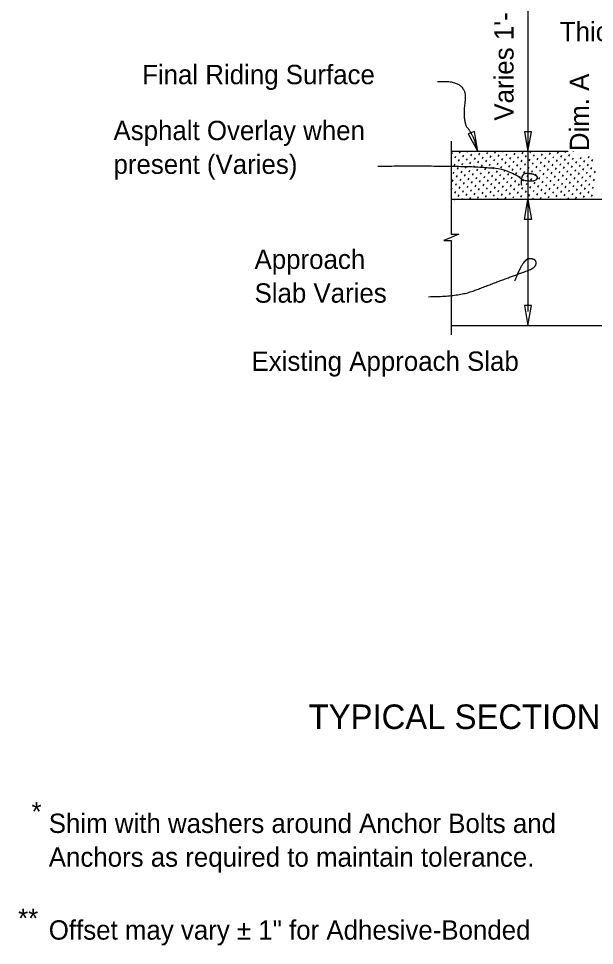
# Model space of a CAD drawing. Extents: x 21629.5 to 21698.8, y 56199.4 to 56237.6.
# Drawn here: x 21650.35 to 21656.36, y 56218.59 to 56228.26 of the extents above; entities that cross this region are included whole.
import ezdxf

# ---------------------------------------------------------------- set-up
doc = ezdxf.new("R2010")
doc.units = 0
for name, color, linetype in [('Dimension', 7, 'Continuous'), ('ExistSuperStruct', 7, 'Continuous'), ('Miscellaneous', 7, 'Continuous'), ('TextStructures', 7, 'Continuous')]:
    doc.layers.add(name, color=color, linetype=linetype)

msp = doc.modelspace()

# ---------------------------------------------------------------- linework, layer by layer
at = {"layer": 'Dimension'}
msp.add_line((21655.6632, 56232.202), (21655.6632, 56225.2019), dxfattribs=at)
for points in [[(21655.1407, 56226.8686), (21655.1069, 56227.0771), (21655.0401, 56227.0543)], [(21655.6634, 56226.8686), (21655.6987, 56227.0769), (21655.6281, 56227.0769)], [(21655.6633, 56226.3686), (21655.6985, 56226.1603), (21655.628, 56226.1603)], [(21655.6633, 56225.0569), (21655.6985, 56225.2652), (21655.628, 56225.2652)]]:
    msp.add_lwpolyline(points, close=True, dxfattribs=at)
msp.add_lwpolyline([(21654.8631, 56226.9778), (21654.8631, 56226.0088), (21654.9406, 56226.0088), (21654.8631, 56225.9751), (21654.7856, 56225.9413), (21654.8631, 56225.9413), (21654.8631, 56224.9569)], dxfattribs=at)
for points in [[(21654.7213, 56227.5984), (21655.0349, 56227.6253), (21654.9791, 56227.1758), (21655.0896, 56227.0538), (21655.1407, 56226.8686)], [(21654.0966, 56226.7169), (21654.4564, 56226.7236), (21655.4463, 56226.7072), (21655.5881, 56226.5767), (21655.693, 56226.5583), (21655.7624, 56226.5767), (21655.7624, 56226.6178), (21655.6916, 56226.6405), (21655.6051, 56226.6405), (21655.588, 56226.5402), (21655.595, 56226.5181)], [(21654.6274, 56225.3564), (21654.9374, 56225.3564), (21655.2737, 56225.485), (21655.5639, 56225.5938), (21655.7486, 56225.6598), (21655.7486, 56225.7521), (21655.6101, 56225.7521), (21655.5244, 56225.518)]]:
    msp.add_open_spline(points, degree=2, dxfattribs=at)
at = {"layer": 'ExistSuperStruct'}
for p, q in [((21658.7963, 56226.3686), (21654.863, 56226.3686)), ((21654.863, 56225.0569), (21660.2645, 56225.0569))]:
    msp.add_line(p, q, dxfattribs=at)
at = {"layer": 'Miscellaneous'}
for p, q in [((21656.0825, 56226.8686), (21654.863, 56226.8686)), ((21654.863, 56226.7712), (21654.8658, 56226.776)), ((21654.8658, 56226.8421), (21654.8755, 56226.8589)), ((21654.9024, 56226.8055), (21654.9121, 56226.8223)), ((21654.939, 56226.7689), (21654.9487, 56226.7857)), ((21654.9487, 56226.8518), (21654.9584, 56226.8686)), ((21654.9853, 56226.8152), (21654.995, 56226.832)), ((21655.0219, 56226.7786), (21655.0316, 56226.7954)), ((21655.0316, 56226.8616), (21655.0357, 56226.8686)), ((21655.0682, 56226.825), (21655.078, 56226.8418)), ((21655.1048, 56226.7884), (21655.1146, 56226.8052)), ((21655.1512, 56226.8347), (21655.1609, 56226.8515)), ((21655.1878, 56226.7981), (21655.1975, 56226.8149)), ((21655.2244, 56226.7615), (21655.2341, 56226.7783)), ((21655.2341, 56226.8444), (21655.2438, 56226.8612)), ((21655.2707, 56226.8078), (21655.2804, 56226.8246)), ((21655.3073, 56226.7712), (21655.317, 56226.788)), ((21655.317, 56226.8541), (21655.3254, 56226.8686)), ((21655.3537, 56226.8175), (21655.3634, 56226.8343)), ((21655.3903, 56226.7809), (21655.4, 56226.7977)), ((21655.4, 56226.8639), (21655.4027, 56226.8686)), ((21655.4366, 56226.8272), (21655.4463, 56226.844)), ((21655.4732, 56226.7906), (21655.4829, 56226.8074)), ((21655.5195, 56226.837), (21655.5293, 56226.8538)), ((21655.5561, 56226.8004), (21655.5659, 56226.8172)), ((21655.5927, 56226.7638), (21655.6025, 56226.7805)), ((21655.6025, 56226.8467), (21655.6122, 56226.8635)), ((21655.6391, 56226.8101), (21655.6488, 56226.8269)), ((21655.6757, 56226.7735), (21655.6854, 56226.7903)), ((21655.6854, 56226.8564), (21655.6925, 56226.8686)), ((21655.722, 56226.8198), (21655.7317, 56226.8366)), ((21655.7586, 56226.7832), (21655.7683, 56226.8)), ((21655.7683, 56226.8661), (21655.7698, 56226.8686)), ((21655.805, 56226.8295), (21655.8147, 56226.8463)), ((21655.8416, 56226.7929), (21655.8513, 56226.8097)), ((21655.8879, 56226.8393), (21655.8976, 56226.856)), ((21655.9245, 56226.8026), (21655.9342, 56226.8194)), ((21655.9611, 56226.766), (21655.9708, 56226.7828)), ((21655.9708, 56226.849), (21655.9805, 56226.8658)), ((21656.0074, 56226.8124), (21656.0172, 56226.8292)), ((21656.044, 56226.7758), (21656.0538, 56226.7926)), ((21656.0538, 56226.8587), (21656.0595, 56226.8686)), ((21656.0904, 56226.8221), (21656.1001, 56226.8389)), ((21656.127, 56226.7855), (21656.1367, 56226.8023)), ((21656.1367, 56226.8684), (21656.1368, 56226.8686)), ((21656.2099, 56226.7952), (21656.2196, 56226.812)), ((21656.2929, 56226.8049), (21656.3026, 56226.8217)), ((21656.3295, 56226.7683), (21656.3392, 56226.7851)), ((21654.8926, 56226.7226), (21654.9024, 56226.7394)), ((21654.9292, 56226.686), (21654.939, 56226.7028)), ((21654.9756, 56226.7323), (21654.9853, 56226.7491)), ((21655.0122, 56226.6957), (21655.0219, 56226.7125)), ((21655.0585, 56226.742), (21655.0682, 56226.7588)), ((21655.0951, 56226.7054), (21655.1048, 56226.7222)), ((21655.1317, 56226.6688), (21655.1414, 56226.6856)), ((21655.1414, 56226.7517), (21655.1512, 56226.7685)), ((21655.1781, 56226.7151), (21655.1878, 56226.7319)), ((21655.2147, 56226.6785), (21655.2244, 56226.6953)), ((21655.261, 56226.7249), (21655.2707, 56226.7417)), ((21655.2976, 56226.6883), (21655.3073, 56226.7051)), ((21655.3439, 56226.7346), (21655.3537, 56226.7514)), ((21655.3805, 56226.698), (21655.3903, 56226.7148)), ((21655.4269, 56226.7443), (21655.4366, 56226.7611)), ((21655.4635, 56226.7077), (21655.4732, 56226.7245)), ((21655.5001, 56226.6711), (21655.5098, 56226.6879)), ((21655.5098, 56226.754), (21655.5195, 56226.7708)), ((21655.5464, 56226.7174), (21655.5561, 56226.7342)), ((21655.583, 56226.6808), (21655.5927, 56226.6976)), ((21655.6294, 56226.7271), (21655.6391, 56226.7439)), ((21655.666, 56226.6905), (21655.6757, 56226.7073)), ((21655.7123, 56226.7369), (21655.722, 56226.7537)), ((21655.7489, 56226.7003), (21655.7586, 56226.7171)), ((21655.7855, 56226.6637), (21655.7952, 56226.6804)), ((21655.7952, 56226.7466), (21655.805, 56226.7634)), ((21655.8318, 56226.71), (21655.8416, 56226.7268)), ((21655.8684, 56226.6734), (21655.8782, 56226.6902)), ((21655.8782, 56226.7563), (21655.8879, 56226.7731)), ((21655.9148, 56226.7197), (21655.9245, 56226.7365)), ((21655.9514, 56226.6831), (21655.9611, 56226.6999)), ((21655.9977, 56226.7294), (21656.0074, 56226.7462)), ((21656.0343, 56226.6928), (21656.044, 56226.7096)), ((21656.0806, 56226.7392), (21656.0904, 56226.7559)), ((21656.1173, 56226.7025), (21656.127, 56226.7193)), ((21656.1539, 56226.6659), (21656.1636, 56226.6827)), ((21656.1636, 56226.7489), (21656.1733, 56226.7657)), ((21656.2002, 56226.7123), (21656.2099, 56226.7291)), ((21656.2368, 56226.6757), (21656.2465, 56226.6925)), ((21656.2465, 56226.7586), (21656.2562, 56226.7754)), ((21656.2831, 56226.722), (21656.2929, 56226.7388)), ((21656.3197, 56226.6854), (21656.3295, 56226.7022)), ((21654.8829, 56226.6396), (21654.8926, 56226.6564)), ((21654.9195, 56226.603), (21654.9292, 56226.6198)), ((21654.9561, 56226.5664), (21654.9659, 56226.5832)), ((21654.9659, 56226.6494), (21654.9756, 56226.6662)), ((21655.0025, 56226.6128), (21655.0122, 56226.6296)), ((21655.0391, 56226.5762), (21655.0488, 56226.5929)), ((21655.0488, 56226.6591), (21655.0585, 56226.6759)), ((21655.0854, 56226.6225), (21655.0951, 56226.6393)), ((21655.122, 56226.5859), (21655.1317, 56226.6027)), ((21655.1683, 56226.6322), (21655.1781, 56226.649)), ((21655.2049, 56226.5956), (21655.2147, 56226.6124)), ((21655.2513, 56226.6419), (21655.261, 56226.6587)), ((21655.2879, 56226.6053), (21655.2976, 56226.6221)), ((21655.3245, 56226.5687), (21655.3342, 56226.5855)), ((21655.3342, 56226.6516), (21655.3439, 56226.6684)), ((21655.3708, 56226.615), (21655.3805, 56226.6318)), ((21655.4074, 56226.5784), (21655.4171, 56226.5952)), ((21655.4171, 56226.6614), (21655.4269, 56226.6782)), ((21655.4538, 56226.6248), (21655.4635, 56226.6416)), ((21655.4904, 56226.5882), (21655.5001, 56226.605)), ((21655.5367, 56226.6345), (21655.5464, 56226.6513)), ((21655.5733, 56226.5979), (21655.583, 56226.6147)), ((21655.6196, 56226.6442), (21655.6294, 56226.661)), ((21655.6562, 56226.6076), (21655.666, 56226.6244)), ((21655.6928, 56226.571), (21655.7026, 56226.5878)), ((21655.7026, 56226.6539), (21655.7123, 56226.6707)), ((21655.7392, 56226.6173), (21655.7489, 56226.6341)), ((21655.7758, 56226.5807), (21655.7855, 56226.5975)), ((21655.8221, 56226.627), (21655.8318, 56226.6438)), ((21655.8587, 56226.5904), (21655.8684, 56226.6072)), ((21655.9051, 56226.6368), (21655.9148, 56226.6536)), ((21655.9417, 56226.6002), (21655.9514, 56226.617)), ((21655.988, 56226.6465), (21655.9977, 56226.6633)), ((21656.0246, 56226.6099), (21656.0343, 56226.6267)), ((21656.0612, 56226.5733), (21656.0709, 56226.5901)), ((21656.0709, 56226.6562), (21656.0806, 56226.673)), ((21656.1075, 56226.6196), (21656.1173, 56226.6364)), ((21656.1441, 56226.583), (21656.1539, 56226.5998)), ((21656.1905, 56226.6293), (21656.2002, 56226.6461)), ((21656.2271, 56226.5927), (21656.2368, 56226.6095)), ((21656.2734, 56226.6391), (21656.2831, 56226.6558)), ((21656.31, 56226.6024), (21656.3197, 56226.6192)), ((21656.3466, 56226.5658), (21656.3563, 56226.5826)), ((21656.3563, 56226.6488), (21656.3661, 56226.6656)), ((21654.8635, 56226.4738), (21654.8732, 56226.4906)), ((21654.8732, 56226.5567), (21654.8829, 56226.5735)), ((21654.9098, 56226.5201), (21654.9195, 56226.5369)), ((21654.9464, 56226.4835), (21654.9561, 56226.5003)), ((21654.9927, 56226.5298), (21655.0025, 56226.5466)), ((21655.0293, 56226.4932), (21655.0391, 56226.51)), ((21655.0757, 56226.5395), (21655.0854, 56226.5563)), ((21655.1123, 56226.5029), (21655.122, 56226.5197)), ((21655.1586, 56226.5493), (21655.1683, 56226.5661)), ((21655.1952, 56226.5127), (21655.2049, 56226.5295)), ((21655.2318, 56226.4761), (21655.2415, 56226.4928)), ((21655.2415, 56226.559), (21655.2513, 56226.5758)), ((21655.2782, 56226.5224), (21655.2879, 56226.5392)), ((21655.3148, 56226.4858), (21655.3245, 56226.5026)), ((21655.3611, 56226.5321), (21655.3708, 56226.5489)), ((21655.3977, 56226.4955), (21655.4074, 56226.5123)), ((21655.444, 56226.5418), (21655.4538, 56226.5586)), ((21655.4806, 56226.5052), (21655.4904, 56226.522)), ((21655.527, 56226.5515), (21655.5367, 56226.5683)), ((21655.5636, 56226.5149), (21655.5733, 56226.5317)), ((21655.6002, 56226.4783), (21655.6099, 56226.4951)), ((21655.6099, 56226.5613), (21655.6196, 56226.5781)), ((21655.6465, 56226.5247), (21655.6562, 56226.5415)), ((21655.6831, 56226.4881), (21655.6928, 56226.5049)), ((21655.7295, 56226.5344), (21655.7392, 56226.5512)), ((21655.7661, 56226.4978), (21655.7758, 56226.5146)), ((21655.8124, 56226.5441), (21655.8221, 56226.5609)), ((21655.849, 56226.5075), (21655.8587, 56226.5243)), ((21655.8856, 56226.4709), (21655.8953, 56226.4877)), ((21655.8953, 56226.5538), (21655.9051, 56226.5706)), ((21655.9319, 56226.5172), (21655.9417, 56226.534)), ((21655.9685, 56226.4806), (21655.9783, 56226.4974)), ((21655.9783, 56226.5636), (21655.988, 56226.5803)), ((21656.0149, 56226.5269), (21656.0246, 56226.5437)), ((21656.0515, 56226.4903), (21656.0612, 56226.5071)), ((21656.0978, 56226.5367), (21656.1075, 56226.5535)), ((21656.1344, 56226.5001), (21656.1441, 56226.5169)), ((21656.1807, 56226.5464), (21656.1905, 56226.5632)), ((21656.2174, 56226.5098), (21656.2271, 56226.5266)), ((21656.254, 56226.4732), (21656.2637, 56226.49)), ((21656.2637, 56226.5561), (21656.2734, 56226.5729)), ((21656.3003, 56226.5195), (21656.31, 56226.5363)), ((21656.3369, 56226.4829), (21656.3466, 56226.4997)), ((21654.863, 56226.4067), (21654.8635, 56226.4076)), ((21654.9001, 56226.4372), (21654.9098, 56226.454)), ((21654.9367, 56226.4006), (21654.9464, 56226.4173)), ((21654.983, 56226.4469), (21654.9927, 56226.4637)), ((21655.0196, 56226.4103), (21655.0293, 56226.4271)), ((21655.0562, 56226.3737), (21655.066, 56226.3905)), ((21655.066, 56226.4566), (21655.0757, 56226.4734)), ((21655.1026, 56226.42), (21655.1123, 56226.4368)), ((21655.1392, 56226.3834), (21655.1489, 56226.4002)), ((21655.1489, 56226.4663), (21655.1586, 56226.4831)), ((21655.1855, 56226.4297), (21655.1952, 56226.4465)), ((21655.2221, 56226.3931), (21655.2318, 56226.4099)), ((21655.2684, 56226.4394), (21655.2782, 56226.4562)), ((21655.305, 56226.4028), (21655.3148, 56226.4196)), ((21655.3514, 56226.4492), (21655.3611, 56226.466)), ((21655.388, 56226.4126), (21655.3977, 56226.4294)), ((21655.4246, 56226.376), (21655.4343, 56226.3927)), ((21655.4343, 56226.4589), (21655.444, 56226.4757)), ((21655.4709, 56226.4223), (21655.4806, 56226.4391)), ((21655.5075, 56226.3857), (21655.5172, 56226.4025)), ((21655.5172, 56226.4686), (21655.527, 56226.4854)), ((21655.5539, 56226.432), (21655.5636, 56226.4488)), ((21655.5905, 56226.3954), (21655.6002, 56226.4122)), ((21655.6368, 56226.4417), (21655.6465, 56226.4585)), ((21655.6734, 56226.4051), (21655.6831, 56226.4219)), ((21655.7197, 56226.4514), (21655.7295, 56226.4682)), ((21655.7563, 56226.4148), (21655.7661, 56226.4316)), ((21655.7929, 56226.3782), (21655.8027, 56226.395)), ((21655.8027, 56226.4612), (21655.8124, 56226.478)), ((21655.8393, 56226.4246), (21655.849, 56226.4414)), ((21655.8759, 56226.388), (21655.8856, 56226.4048)), ((21655.9222, 56226.4343), (21655.9319, 56226.4511)), ((21655.9588, 56226.3977), (21655.9685, 56226.4145)), ((21656.0052, 56226.444), (21656.0149, 56226.4608)), ((21656.0418, 56226.4074), (21656.0515, 56226.4242)), ((21656.0881, 56226.4537), (21656.0978, 56226.4705)), ((21656.1247, 56226.4171), (21656.1344, 56226.4339)), ((21656.1613, 56226.3805), (21656.171, 56226.3973)), ((21656.171, 56226.4635), (21656.1807, 56226.4802)), ((21656.2076, 56226.4268), (21656.2174, 56226.4436)), ((21656.2442, 56226.3902), (21656.254, 56226.407)), ((21656.2906, 56226.4366), (21656.3003, 56226.4534)), ((21656.3272, 56226.4), (21656.3369, 56226.4168)), ((21654.8987, 56226.3686), (21654.9001, 56226.371)), ((21654.976, 56226.3686), (21654.983, 56226.3807)), ((21655.2657, 56226.3686), (21655.2684, 56226.3733)), ((21655.343, 56226.3686), (21655.3514, 56226.383)), ((21655.6327, 56226.3686), (21655.6368, 56226.3756)), ((21655.71, 56226.3686), (21655.7197, 56226.3853)), ((21655.9998, 56226.3686), (21656.0052, 56226.3779)), ((21656.0784, 56226.3708), (21656.0881, 56226.3876)), ((21656.2895, 56226.3686), (21656.2906, 56226.3704))]:
    msp.add_line(p, q, dxfattribs=at)

# ---------------------------------------------------------------- texts
at = {"layer": 'Dimension'}
for s, height, p in [('Thick Neoprene Pad', 0.2016, (21655.9955, 56228.0196)), ('Asphalt Overlay when', 0.2016, (21651.341, 56226.9889)), ('present (Varies)', 0.2016, (21651.341, 56226.6369)), ('Approach', 0.2016, (21652.8118, 56225.6459)), ('Slab Varies', 0.2016, (21652.8118, 56225.2939)), ('TYPICAL SECTION THRU RAILING ALONG APPROACH SLAB', 0.256001, (21653.3761, 56220.8486)), ('Shim with washers around Anchor Bolts and', 0.2016, (21650.6658, 56219.7649)), ('Anchors as required to maintain tolerance.', 0.2016, (21650.6658, 56219.4129)), ('Offset may vary ± 1" for Adhesive-Bonded', 0.2016, (21650.6658, 56218.6526))]:
    msp.add_text(s, height=height, dxfattribs=at).set_placement(p)
at = {"layer": 'TextStructures'}
for s, p in [('Varies 1\'-9" to 2\'-0"', (21655.5133, 56227.1914)), ('Dim. A', (21656.3009, 56226.8737))]:
    msp.add_text(s, height=0.2016, rotation=90, dxfattribs=at).set_placement(p)
for s, p in [('Final Riding Surface', (21651.6391, 56227.572)), ('Existing Approach Slab', (21652.7804, 56224.5832)), ('*', (21650.4859, 56219.8872)), ('**', (21650.3461, 56218.7749))]:
    msp.add_text(s, height=0.2016, dxfattribs=at).set_placement(p)

doc.saveas('drawing.dxf')
